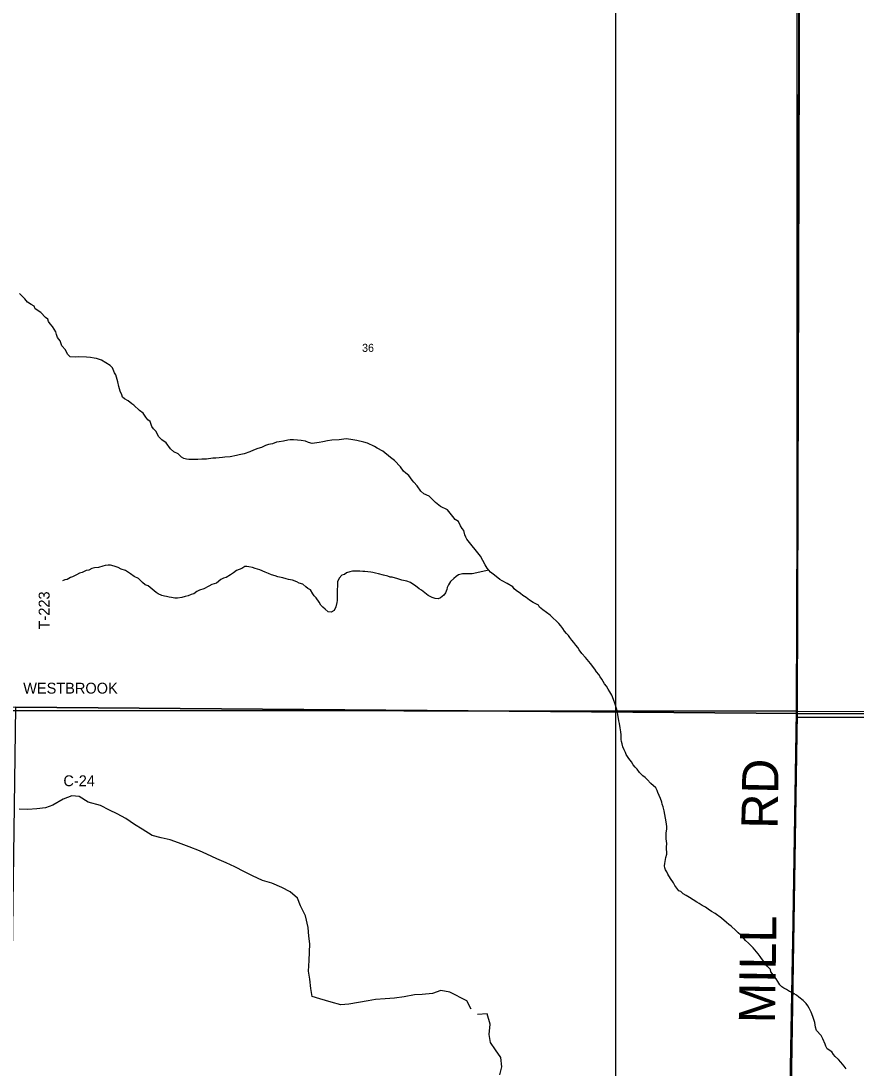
# Model space of a CAD drawing. Extents: x 1312308 to 1684953, y 460642 to 865172.
# Drawn here: x 1438818 to 1444582, y 670241 to 677470 of the extents above; entities that cross this region are included whole.
import ezdxf

# ---------------------------------------------------------------- set-up
doc = ezdxf.new("R2010")
doc.units = 0
for name, color, linetype in [('GM_X_City_Street', 7, 'Continuous'), ('GM_X_Corporation', 7, 'Continuous'), ('GM_X_County_Road', 7, 'Continuous'), ('GM_X_County_Road_Text', 7, 'Continuous'), ('GM_X_Minor_River', 7, 'Continuous'), ('GM_X_Section', 7, 'Continuous'), ('GM_X_Section_Text', 7, 'Continuous'), ('GM_X_Township', 7, 'Continuous'), ('GM_X_Township_Road_Text', 7, 'Continuous'), ('SH_Data', 7, 'Continuous')]:
    doc.layers.add(name, color=color, linetype=linetype)

msp = doc.modelspace()

# ---------------------------------------------------------------- linework, layer by layer
at = {"layer": 'GM_X_City_Street'}
msp.add_lwpolyline([(1444171.3, 672705.1), (1449086.5, 672689.4), (1449320.9, 672690.2), (1451706.5, 672673), (1453014.7, 672675.7), (1454404.6, 672672.9)], dxfattribs=at)
at = {"layer": 'GM_X_Corporation'}
for points in [[(1475856.8, 672568.7), (1444174.8, 672664), (1444174.8, 673775.3), (1444174.8, 674127.5), (1444174.7, 674750.1), (1444174.4, 680999.8), (1444007.7, 681035.5), (1444023.9, 682884.1), (1443976.5, 683288.7), (1443962.3, 683833.1), (1443758.9, 683960.3), (1443761, 684493.9), (1443998.9, 684351.1), (1444063.4, 684654.8), (1444174.2, 684716.2), (1444172.9, 704885.4), (1458948.6, 704881.7)], [(1470357.1, 641048.9), (1443692.6, 641278.6), (1443717.6, 642811.7), (1443736.3, 643927.4), (1443816.9, 652104.2), (1443987.8, 662312.5), (1444085.7, 667768), (1444130.8, 670246.6), (1444144.6, 671004.1), (1444174.8, 672664), (1475856.8, 672568.7)]]:
    msp.add_lwpolyline(points, dxfattribs=at)
at = {"layer": 'GM_X_County_Road'}
for points in [[(1444171.3, 672705.1), (1444189.4, 677948.3), (1444189.5, 678014.9), (1444196.1, 680400.4)], [(1438802.3, 672709.6), (1444171.3, 672705.1)], [(1443907.6, 656018.7), (1443921, 657078.9), (1443923.3, 657173.2), (1443962.5, 659813.5), (1443986.4, 660665.8), (1444017.3, 662315.4), (1444059.5, 665133.4), (1444094, 667790), (1444097.3, 668076.3), (1444171.3, 672705.1)]]:
    msp.add_lwpolyline(points, dxfattribs=at)
at = {"layer": 'GM_X_Minor_River'}
for points in [[(1439434.7, 675091.3), (1439375.5, 675128.9), (1439339.8, 675139.8), (1439323.8, 675142.2), (1439297.9, 675146.8), (1439269.9, 675149.5), (1439217.9, 675150.8), (1439195.8, 675149.3), (1439157.8, 675150.3), (1439140.2, 675170.7), (1439124.9, 675199.2), (1439101.6, 675227.8), (1439088.4, 675262.2), (1439070.9, 675284.7), (1439063.4, 675304.9), (1439059.8, 675323), (1439036.8, 675361.7), (1439021.1, 675378.1), (1439007.5, 675394.5), (1439003.9, 675410.6), (1438988.2, 675423), (1438955, 675457.9), (1438915.6, 675482.9), (1438910, 675501.1), (1438888.2, 675511.7), (1438862.6, 675528.3), (1438845.1, 675550.8), (1438808, 675587.8)], [(1441990.6, 673774.9), (1441896.9, 673892.2), (1441889.2, 673906.4), (1441881.6, 673922.7), (1441874.3, 673952.9), (1441862.6, 673967.2), (1441853, 673983.5), (1441837.7, 674013.9), (1441816.1, 674028.5), (1441798.6, 674049), (1441761.7, 674096), (1441714.2, 674119.2), (1441678.8, 674146.2), (1441635.8, 674189.3), (1441600.1, 674206.2), (1441578.5, 674224.8), (1441553.4, 674261.5), (1441530, 674286.1), (1441518.3, 674300.4), (1441495.1, 674333.1), (1441475.4, 674347.6), (1441459.7, 674362), (1441438.5, 674392.6), (1441397.5, 674435.7), (1441369.9, 674456.4), (1441316.9, 674499.8), (1441277.4, 674520.8), (1441259.6, 674531.3), (1441210.1, 674554.6), (1441184.2, 674561.2), (1441136.5, 674574.4), (1441094.6, 674581.5), (1441062.6, 674584.3), (1441014.4, 674579.4), (1440964.3, 674576.7), (1440934.1, 674571.4), (1440901.9, 674564.2), (1440875.8, 674560.8), (1440859.7, 674557.2), (1440843.6, 674555.6), (1440829.5, 674553.9), (1440803.7, 674560.6), (1440781.8, 674569.1), (1440751.9, 674573.9), (1440727.9, 674576.5), (1440700, 674579.2), (1440675.9, 674577.7), (1440659.8, 674576.1), (1440629.6, 674568.9), (1440601.5, 674565.5), (1440581.4, 674562), (1440555.1, 674550.7), (1440526.9, 674545.3), (1440506.7, 674539.8), (1440478.3, 674524.5), (1440454.2, 674519.1), (1440423.8, 674507.8), (1440397.5, 674494.4), (1440359.1, 674481.3), (1440324.9, 674474.1), (1440306.8, 674470.6), (1440262.5, 674461.7), (1440226.3, 674458.5), (1440210.3, 674456.9), (1440164.1, 674452), (1440142, 674450.6), (1440099.9, 674445.6), (1440065.8, 674444.4), (1440039.7, 674443.1), (1440005.6, 674441.9), (1439977.6, 674442.6), (1439961.6, 674445), (1439941.7, 674449.5), (1439925.9, 674457.9), (1439904.5, 674482.5), (1439874.7, 674495.2), (1439851.2, 674515.9), (1439820.2, 674556.7), (1439790.6, 674577.5), (1439771.1, 674598), (1439750.1, 674638.6), (1439732.4, 674653.1), (1439722.8, 674671.4), (1439709.6, 674703.8), (1439693.9, 674716.2), (1439680.3, 674734.5), (1439661, 674763.1), (1439637.4, 674779.7), (1439598.2, 674816.7), (1439584.5, 674827.1), (1439558.9, 674847.8), (1439533.3, 674862.4), (1439519.5, 674872.8), (1439513.9, 674889), (1439502.5, 674915.3), (1439493.3, 674947.6), (1439488.1, 674979.8), (1439473.2, 675026.3), (1439463.5, 675040.5), (1439450.3, 675074.9), (1439434.7, 675091.3)], [(1439900, 673486.1), (1439879.9, 673484.6), (1439858, 673489.1), (1439842, 673491.5), (1439824.1, 673496), (1439808.2, 673498.4), (1439790.3, 673504.8), (1439766.5, 673515.4), (1439752.7, 673523.8), (1439725.2, 673546.5), (1439695.7, 673569.3), (1439675.9, 673577.8), (1439658.3, 673592.3), (1439630.9, 673621), (1439599.2, 673635.8), (1439573.6, 673652.5), (1439540.1, 673675.4), (1439510.3, 673686.1), (1439488.6, 673696.7), (1439462.8, 673707.3), (1439436.9, 673712), (1439420.9, 673712.4), (1439400.8, 673710.9), (1439382.7, 673707.3), (1439354.4, 673698), (1439326.3, 673694.7), (1439308.1, 673689.1), (1439285.9, 673679.6), (1439267.8, 673676), (1439241.4, 673662.7), (1439223.2, 673657.1), (1439202.9, 673645.6), (1439188.8, 673639.9), (1439174.5, 673632.2), (1439160.4, 673628.6), (1439138.1, 673615.1), (1439122, 673611.5), (1439105.8, 673603.8)], [(1442397.6, 673422.3), (1442389.8, 673436.5), (1442354.1, 673455.2), (1442328.4, 673471.7), (1442304.7, 673490.2), (1442282.9, 673504.6), (1442265.1, 673517), (1442237.4, 673537.6), (1442223.6, 673549.9), (1442213.8, 673564.1), (1442174.2, 673586.9), (1442140.4, 673605.5), (1442122.5, 673613.9), (1442098.9, 673634.4), (1442077.1, 673650.8), (1442059.8, 673664.2), (1442048.2, 673678.8), (1442036.7, 673692), (1442022.3, 673715.4), (1441990.6, 673774.9)], [(1442048.2, 673678.8), (1441933, 673652.5), (1441882.9, 673653.7), (1441864.9, 673652.2), (1441838.7, 673646.8), (1441822.4, 673635.2), (1441806, 673621.6), (1441783.5, 673600.1), (1441768.9, 673578.4), (1441760.4, 673558.5), (1441758.1, 673544.6), (1441749.5, 673522.7), (1441737.1, 673507), (1441714.6, 673487.5), (1441698.4, 673479.9), (1441678.4, 673482.4), (1441656.6, 673490.9), (1441628.9, 673503.6), (1441583.7, 673540.8), (1441565.9, 673549.3), (1441542.4, 673569.9), (1441522.7, 673582.4), (1441506.9, 673592.8), (1441481.1, 673603.5), (1441447.2, 673610.4), (1441419.4, 673619.1), (1441381.6, 673630), (1441365.6, 673630.4), (1441351.7, 673636.8), (1441319.9, 673643.6), (1441286, 673652.4), (1441266.2, 673658.9), (1441246.2, 673661.4), (1441232.2, 673663.8), (1441192.3, 673668.8), (1441178.3, 673669.1), (1441158.3, 673671.6), (1441120.3, 673672.5), (1441106.2, 673670.9), (1441088.1, 673667.3), (1441065.9, 673659.8), (1441051.6, 673648.2), (1441033.5, 673644.6), (1441014.9, 673623), (1441004.3, 673597.2), (1441003.7, 673575.2), (1441000.8, 673537.2), (1441001.9, 673501), (1441001.1, 673469), (1440998.8, 673455), (1440992.1, 673425.1), (1440979.4, 673399.4), (1440959.1, 673387.8), (1440939.1, 673390.3), (1440917.5, 673408.9), (1440901.9, 673423.3), (1440888.2, 673437.7), (1440876.7, 673458), (1440855.4, 673488.6), (1440841.7, 673501), (1440832, 673515.2), (1440816.7, 673541.7), (1440798.9, 673552.2), (1440785.1, 673562.5), (1440763.5, 673581.1), (1440739.7, 673589.7), (1440721.9, 673598.2), (1440692.1, 673608.9), (1440664.2, 673613.6), (1440648.3, 673618), (1440626.5, 673626.6), (1440590.6, 673633.5), (1440572.7, 673639.9), (1440548.8, 673646.5), (1440527, 673655.1), (1440503.2, 673665.7), (1440467.6, 673680.6), (1440435.7, 673689.4), (1440415.9, 673697.9), (1440392, 673702.5), (1440378, 673704.8), (1440364, 673703.2), (1440343.6, 673689.7), (1440307.2, 673676.5), (1440284.8, 673661), (1440264.5, 673647.5), (1440233.9, 673628.2), (1440215.8, 673622.6), (1440197.5, 673613.1), (1440168.9, 673587.7), (1440136.6, 673578.5), (1440114.3, 673569), (1440081.8, 673549.8), (1440051.5, 673540.5), (1440033.3, 673530.9), (1440010.9, 673515.4), (1439992.7, 673509.9), (1439972.5, 673502.3), (1439952.3, 673496.8), (1439928.1, 673489.4), (1439900, 673486.1)], [(1443688.2, 671246.8), (1443652.7, 671275.5), (1443609.2, 671308.4), (1443585.4, 671322.9), (1443561.7, 671339.4), (1443541.9, 671351.8), (1443520, 671364.3), (1443500.2, 671376.7), (1443482.4, 671387), (1443432.8, 671418), (1443409.1, 671432.5), (1443389.2, 671444.9), (1443373.5, 671459.2), (1443359.6, 671465.5), (1443332.2, 671502.2), (1443322.5, 671520.4), (1443301, 671550.9), (1443283.5, 671579.3), (1443275.8, 671595.5), (1443268, 671609.7), (1443262.3, 671623.9), (1443260.5, 671638), (1443262.8, 671654), (1443265.1, 671668), (1443269.6, 671694.1), (1443276, 671718), (1443274.9, 671766.3), (1443275.4, 671792.4), (1443272, 671824.6), (1443272.7, 671864.7), (1443275.2, 671890.8), (1443275.6, 671908.8), (1443272.2, 671941), (1443257.5, 672017.6), (1443250, 672045.8), (1443244.4, 672064), (1443240.6, 672078.1), (1443233.1, 672102.4), (1443213.7, 672142.9), (1443210, 672157), (1443200.3, 672175.2), (1443164.8, 672206), (1443139.3, 672232.5), (1443125.5, 672246.8), (1443109.7, 672259.2), (1443088.1, 672281.7), (1443070.4, 672304), (1443058.7, 672318.3), (1443044.9, 672334.6), (1443031.3, 672354.9), (1443013.7, 672377.3), (1443003.9, 672391.6), (1442996.1, 672405.8), (1442990.4, 672419.9), (1442982.7, 672438.1), (1442973.1, 672458.4), (1442967.4, 672478.6), (1442963.7, 672494.7), (1442960, 672508.8), (1442960.6, 672540.9), (1442959, 672563), (1442953.4, 672589.2), (1442950, 672619.4), (1442944.3, 672639.6), (1442942.6, 672655.7), (1442939.1, 672679.8), (1442935.4, 672698), (1442927.9, 672724.2), (1442920.4, 672754.5), (1442909, 672786.8), (1442897.5, 672815.1), (1442883.9, 672839.5), (1442872.2, 672857.7), (1442860.6, 672878), (1442846.8, 672894.3), (1442827.4, 672926.8), (1442815.6, 672941.1), (1442805.9, 672957.3), (1442790.2, 672977.7), (1442778.6, 672995.9), (1442749.2, 673034.6), (1442713.9, 673075.4), (1442688.4, 673103.9), (1442670.8, 673128.3), (1442661, 673144.6), (1442647.3, 673160.9), (1442633.6, 673179.2), (1442619.9, 673195.5), (1442606.2, 673213.8), (1442596.4, 673228), (1442584.7, 673242.3), (1442571, 673258.6), (1442559.3, 673276.9), (1442545.5, 673293.2), (1442529.8, 673311.5), (1442512.1, 673329.9), (1442492.4, 673348.3), (1442470.7, 673366.8), (1442445.1, 673387.3), (1442421.3, 673403.8), (1442397.6, 673422.3)], [(1441925.8, 670647.5), (1441896.3, 670704.8), (1441777.4, 670764.7), (1441715.4, 670776.6), (1441658.4, 670756.2), (1441587.7, 670748.3), (1441535.3, 670745.9), (1441464.4, 670733.9), (1441397.7, 670723.9), (1441331.2, 670719.9), (1441266.6, 670715.8), (1441216, 670705.3), (1441149.2, 670693.3), (1441082.4, 670683.2), (1441025.9, 670676.9), (1440960.1, 670697), (1440882.2, 670719.4), (1440828.4, 670735.1), (1440820, 670789.7), (1440811.9, 670854.2), (1440803.6, 670910.7), (1440807.9, 670985), (1440811.4, 671099.4), (1440805, 671151.8), (1440800.8, 671212.2), (1440783.2, 671293.2), (1440749, 671360.5), (1440726.5, 671413.4), (1440675.5, 671457.2), (1440620, 671487), (1440550.5, 671517.2), (1440486.7, 671537.2), (1440417.2, 671567.5), (1440361.7, 671595.3), (1440294.3, 671631.5), (1440234.7, 671657.4), (1440171.2, 671685.4), (1440101.7, 671717.7), (1440050.1, 671741.3), (1439978.5, 671769.6), (1439906.9, 671795.9), (1439849.2, 671817.7), (1439787.1, 671829.7), (1439723.3, 671847.7), (1439654.1, 671889.9), (1439602.8, 671923.7), (1439541.6, 671963.7), (1439482.2, 671995.6), (1439430.7, 672021.3), (1439367.2, 672053.3), (1439281.4, 672078), (1439220.2, 672116), (1439170, 672119.6), (1439108.9, 672097.3), (1439039.2, 672055.2), (1438988.3, 672038.7), (1438927.7, 672030.5), (1438865.2, 672026.3), (1438806.8, 672028.1)], [(1444513.3, 670235.7), (1444499.6, 670254.1), (1444476.1, 670282.6), (1444460.4, 670301), (1444438.7, 670321.4), (1444426.9, 670335.7), (1444415.3, 670354), (1444383.6, 670374.7), (1444373.9, 670392.9), (1444368.1, 670407.1), (1444352.8, 670443.5), (1444341.2, 670465.8), (1444309.7, 670500.5), (1444302.2, 670524.8), (1444300.5, 670540.9), (1444296.8, 670557), (1444283.5, 670597.4), (1444272, 670627.8), (1444258.5, 670654.1), (1444248.8, 670670.4), (1444237, 670686.7), (1444217.4, 670707.1), (1444187.8, 670731.7), (1444170, 670744.1), (1444154.1, 670754.4), (1444140.2, 670762.7), (1444122.3, 670771), (1444102.5, 670783.4), (1444084.7, 670791.8), (1444070.8, 670802.1), (1444057, 670816.4), (1444041.4, 670838.8), (1444029.7, 670857.1), (1443994.6, 670905.9), (1443990.9, 670922), (1443969.2, 670944.5), (1443955.5, 670962.8), (1443945.8, 670977.1), (1443930.1, 670997.4), (1443920.4, 671011.7), (1443906.7, 671030), (1443871.4, 671070.8), (1443853.7, 671089.2), (1443839.9, 671103.5), (1443820.2, 671121.9), (1443798.6, 671146.4), (1443784.8, 671160.7), (1443769.1, 671175), (1443751.3, 671191.4), (1443719.8, 671220.1), (1443704, 671232.4), (1443688.2, 671246.8)], [(1442123.4, 670195.2), (1442138.5, 670249.2), (1442129.8, 670313.7), (1442094.8, 670366.6), (1442059.7, 670417.6), (1442050.8, 670472), (1442056.3, 670544.2), (1442035.7, 670615), (1441969.4, 670612.2)]]:
    msp.add_lwpolyline(points, dxfattribs=at)
at = {"layer": 'GM_X_Section'}
for points in [[(1444186.9, 678005.5), (1444191.8, 677949.4), (1444175.9, 672688), (1438782.3, 672733.5), (1438508.2, 672731.4), (1438497.9, 678017.5)], [(1449351.4, 677945.7), (1449323.6, 672686.6), (1449097.4, 672677.1), (1444175.9, 672688), (1444191.8, 677949.4)], [(1438782.3, 672733.5), (1444175.9, 672688), (1444097.4, 667787.9), (1444089, 667570.1), (1438714.7, 667639.1)], [(1444175.9, 672688), (1449097.4, 672677.1), (1449206.8, 667577.3), (1444097.4, 667787.9)]]:
    msp.add_lwpolyline(points, close=True, dxfattribs=at)
at = {"layer": 'GM_X_Township'}
for points in [[(1444196.7, 685936.8), (1444204.1, 683929), (1444202.4, 683302.8), (1444202.7, 682997.9), (1444199.7, 681781.4), (1444197.6, 680925.7), (1444189.5, 678014.9), (1444189.4, 677948.3), (1444171.3, 672705.1), (1438749.2, 672709.6), (1438494.5, 672731.6), (1436580.2, 672721.5), (1435620.2, 672741.2), (1434940.6, 672743.7)], [(1434940.6, 672743.7), (1435620.2, 672741.2), (1436580.2, 672721.5), (1438494.5, 672731.6), (1438749.2, 672709.6), (1444171.3, 672705.1), (1444097.3, 668076.3)]]:
    msp.add_lwpolyline(points, dxfattribs=at)
at = {"layer": 'SH_Data'}
msp.add_line((1442922.2, 682555.4), (1442922.2, 664603.4), dxfattribs=at)

# ---------------------------------------------------------------- texts
at = {"layer": 'GM_X_County_Road_Text'}
for s, height, rotation, p in [('WESTBROOK', 75, 0.00001, (1438834.2, 672826.4)), ('RD', 250, 89.01181, (1444040.2, 671892)), ('C-24', 75, 0.00001, (1439111.4, 672187.1)), ('MILL', 250, 89.19675, (1444022.6, 670549.6))]:
    msp.add_text(s, height=height, rotation=rotation, dxfattribs=at).set_placement(p)
at = {"layer": 'GM_X_Section_Text'}
msp.add_text('36', height=55.25, rotation=0.00001, dxfattribs=at).set_placement((1441172.7, 675185.8))
at = {"layer": 'GM_X_Township_Road_Text'}
msp.add_text('T-223', height=75, rotation=90.01021, dxfattribs=at).set_placement((1439016, 673269.7))

doc.saveas('drawing.dxf')
